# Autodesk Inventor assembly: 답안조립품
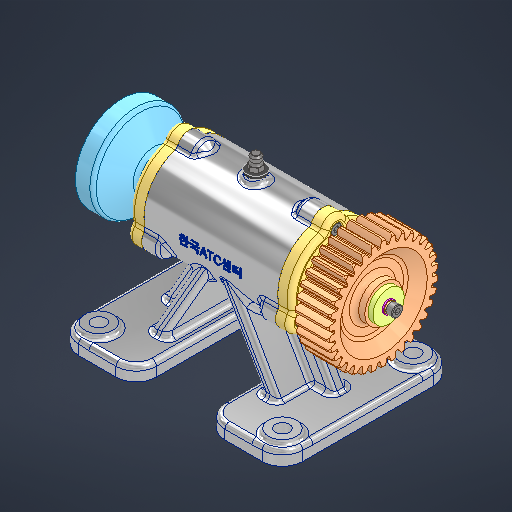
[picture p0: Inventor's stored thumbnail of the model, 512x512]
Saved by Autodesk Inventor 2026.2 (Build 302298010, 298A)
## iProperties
Created: 2026-04
Part Number: 답안조립품
Document SubType Name: Assembly
Designer: PC2-02
Author: PC2-02
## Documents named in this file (16)
- C:\Users\PC2-02\Desktop\760403V1012\답안조립품.iam
- C:\Users\PC2-02\Desktop\760403V1012\본체.ipt
- C:\Users\PC2-02\Desktop\760403V1012\6각 구멍붙이 볼트 M4x12\6각 구멍붙이 볼트 M4x12.ipt
- C:\Users\PC2-02\Desktop\760403V1012\그리스 니플 M6x0,75\그리스 니플 M6x0,75.ipt
- C:\Users\PC2-02\Desktop\760403V1012\깊은 홈 볼 베어링 6004\깊은 홈 볼 베어링 6004.ipt
- C:\Users\PC2-02\Desktop\760403V1012\스퍼 기어\스퍼 기어.ipt
- C:\Users\PC2-02\Desktop\760403V1012\스프링 와셔 M4\스프링 와셔 M4.ipt
- C:\Users\PC2-02\Desktop\760403V1012\실링\실링.ipt
- C:\Users\PC2-02\Desktop\760403V1012\엔드 캡\엔드 캡.ipt
- C:\Users\PC2-02\Desktop\760403V1012\오일 실 20 35 8\오일 실 20 35 8.ipt
- C:\Users\PC2-02\Desktop\760403V1012\축\축.ipt
- C:\Users\PC2-02\Desktop\760403V1012\커버\커버.ipt
- C:\Users\PC2-02\Desktop\760403V1012\평 와셔 M4\평 와셔 M4.ipt
- C:\Users\PC2-02\Desktop\760403V1012\평행 키 4x4x14\평행 키 4x4x14.ipt
- C:\Users\PC2-02\Desktop\760403V1012\플랜지\플랜지.ipt
- C:\Users\PC2-02\Desktop\760403V1012\플러그 M6x0,75\플러그 M6x0,75.ipt
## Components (11 placed, 4 different names)
1. 6각 구멍붙이 볼트 M4x12:1
2. 그리스 니플 M6x0,75:1
3. 플랜지:1
4. 플러그 M6x0,75:1
5. 6각 구멍붙이 볼트 M4x12:2
6. 6각 구멍붙이 볼트 M4x12:3
7. 6각 구멍붙이 볼트 M4x12:4
8. 6각 구멍붙이 볼트 M4x12:5
9. 6각 구멍붙이 볼트 M4x12:6
10. 6각 구멍붙이 볼트 M4x12:7
11. 6각 구멍붙이 볼트 M4x12:8
